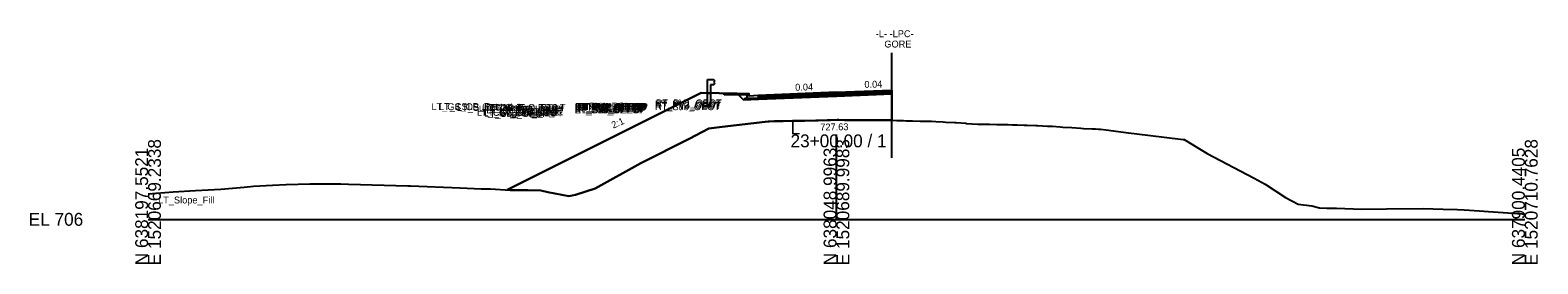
# Model space of a CAD drawing. Extents: x -26 to 3903, y -10 to 9531.
# Drawn here: x 974.3 to 1302.8, y 2990.3 to 3041.2 of the extents above; entities that cross this region are included whole.
import ezdxf

# ---------------------------------------------------------------- set-up
doc = ezdxf.new("R2010")
doc.units = 0
for name, color, linetype in [('Default', 7, 'Continuous'), ('Exist Cross Section Cell', 7, 'Continuous'), ('Exist XS Center Line Elevation Label', 7, 'Continuous'), ('Exist XS Ground Line', 7, 'Continuous'), ('Old_Level_63', 7, 'Continuous'), ('Prop CMT Conc Surface', 7, 'Continuous'), ('Prop CMT Guardrail Graphics', 7, 'Continuous'), ('Prop CMT Pvmt Course 1', 7, 'Continuous'), ('Prop CMT Pvmt Course 1 CG', 7, 'Continuous'), ('Prop CMT Pvmt Course 2', 7, 'Continuous'), ('Prop CMT Pvmt Course 3', 7, 'Continuous'), ('Prop CMT Pvmt Surface', 7, 'Continuous'), ('Prop CMT Shld Paved Course 1', 7, 'Continuous'), ('Prop CMT Shld Paved Course 2', 7, 'Continuous'), ('Prop CMT Shld Paved Course 3', 7, 'Continuous'), ('Prop CMT Slope Grass', 7, 'Continuous'), ('Prop CMT Subgrade Earthwork', 7, 'Continuous'), ('Prop XS Earthwork Shape', 7, 'Continuous'), ('Prop XS Finish Grade Concrete', 7, 'Continuous'), ('Prop XS SE Text', 7, 'Continuous'), ('Prop XS Shear Point Element', 7, 'Continuous'), ('Prop XS Side Slope Text', 7, 'Continuous')]:
    doc.layers.add(name, color=color, linetype=linetype)

msp = doc.modelspace()

# ---------------------------------------------------------------- linework, layer by layer
at = {"layer": 'Exist Cross Section Cell'}
for p, q in [((1150, 3000), (1150, 3018.49)), ((1000, 3000), (1150, 3000)), ((1150, 3000), (1300, 3000))]:
    msp.add_line(p, q, dxfattribs=at)
at = {"layer": 'Exist XS Ground Line'}
msp.add_lwpolyline([(1000, 3005.56), (1005.44, 3005.96), (1010.37, 3006.29), (1015.83, 3006.6), (1020.96, 3007.01), (1022.98, 3007.19), (1027.15, 3007.41), (1030.11, 3007.62), (1035.24, 3007.72), (1040, 3007.74), (1041.97, 3007.72), (1043.66, 3007.65), (1056.64, 3007.29), (1056.97, 3007.27), (1057.06, 3007.27), (1057.21, 3007.27), (1068.02, 3006.84), (1072.55, 3006.65), (1074.61, 3006.62), (1078.92, 3006.37), (1082.73, 3006.36), (1085.57, 3006.29), (1087.12, 3005.94), (1091.72, 3005.02), (1093.13, 3005.35), (1097.46, 3006.75), (1107.37, 3012.26), (1117.93, 3017.54), (1122.17, 3019.77), (1125.12, 3020.12), (1134.46, 3021.25), (1135.13, 3021.33), (1135.21, 3021.33), (1135.33, 3021.34), (1136.44, 3021.39), (1136.48, 3021.39), (1136.64, 3021.39), (1137.91, 3021.4), (1138.41, 3021.41), (1140.45, 3021.44), (1142.18, 3021.46), (1142.85, 3021.47), (1142.95, 3021.47), (1143.07, 3021.47), (1145.48, 3021.51), (1146.04, 3021.53), (1148, 3021.58), (1148.74, 3021.6), (1150.18, 3021.64), (1150.44, 3021.64), (1150.55, 3021.64), (1151.73, 3021.63), (1153.07, 3021.63), (1153.95, 3021.62), (1155.6, 3021.61), (1157.78, 3021.6), (1158.11, 3021.6), (1160.17, 3021.59), (1160.58, 3021.59), (1160.64, 3021.59), (1160.71, 3021.59), (1163.16, 3021.54), (1163.53, 3021.54), (1164.62, 3021.52), (1165.16, 3021.49), (1165.7, 3021.47), (1166.61, 3021.44), (1168.22, 3021.4), (1169.53, 3021.38), (1170.75, 3021.35), (1171.66, 3021.31), (1173.27, 3021.21), (1173.85, 3021.18), (1175.77, 3021.08), (1176.09, 3021.07), (1178.2, 3020.92), (1178.32, 3020.91), (1178.34, 3020.91), (1180.84, 3020.76), (1181.27, 3020.75), (1183.36, 3020.71), (1184.94, 3020.68), (1185.88, 3020.67), (1186.77, 3020.66), (1187.28, 3020.65), (1187.4, 3020.64), (1188.4, 3020.61), (1189.37, 3020.58), (1190.91, 3020.54), (1191.58, 3020.52), (1193.43, 3020.46), (1193.79, 3020.44), (1195.96, 3020.33), (1195.98, 3020.33), (1196.86, 3020.29), (1197.1, 3020.27), (1198.77, 3020.14), (1199.35, 3020.1), (1201.29, 3019.97), (1203.27, 3019.86), (1203.83, 3019.82), (1205.72, 3019.73), (1206.21, 3019.7), (1206.42, 3019.69), (1207.07, 3019.65), (1207.57, 3019.61), (1208.75, 3019.48), (1209.82, 3019.32), (1213.67, 3018.85), (1217.87, 3018.33), (1225.56, 3017.42), (1225.71, 3017.41), (1225.79, 3017.39), (1230.79, 3014.31), (1239.49, 3009.79), (1241.01, 3008.97), (1242.59, 3008.11), (1243.4, 3007.65), (1247.87, 3004.75), (1250.64, 3003.29), (1253.6, 3002.93), (1255.26, 3002.52), (1256.86, 3002.44), (1259, 3002.46), (1264.47, 3002.25), (1269.85, 3002.29), (1277.84, 3002.37), (1282.18, 3002.24), (1285.31, 3002.14), (1286.82, 3002.06), (1287.92, 3001.97), (1299.42, 3001.2), (1300, 3001.16)], dxfattribs=at)
at = {"layer": 'Old_Level_63'}
for p, q in [((1131.01, 3026.85), (1131.01, 3027.35)), ((1133.01, 3027.01), (1131.01, 3026.85)), ((1162.07, 3028.17), (1162.07, 3021.57))]:
    msp.add_line(p, q, dxfattribs=at)
for points in [[(1125.51, 3027.12), (1125.51, 3027.46)], [(1130.51, 3027.02), (1125.51, 3027.12)], [(1130.51, 3027.02), (1125.51, 3027.12)], [(1130.51, 3027.35), (1130.51, 3026.32), (1133.01, 3026.42)], [(1133.01, 3026.42), (1133.01, 3027.01)]]:
    msp.add_lwpolyline(points, dxfattribs=at)
at = {"layer": 'Prop CMT Conc Surface'}
for points in [[(1130.93, 3026.84), (1130.93, 3027.34), (1130.43, 3027.34)], [(1132.93, 3027), (1130.93, 3026.84)], [(1080.93, 3023.84), (1080.93, 3024.34), (1080.43, 3024.34)], [(1082.93, 3024), (1080.93, 3023.84)]]:
    msp.add_lwpolyline(points, dxfattribs=at)
at = {"layer": 'Prop CMT Guardrail Graphics'}
for points in [[(1121.9, 3024.47), (1121.9, 3030.47)], [(1121.9, 3030.47), (1123.23, 3030.47), (1123.5, 3030.18)], [(1123.5, 3029.6), (1123.23, 3029.31), (1122.56, 3029.31)], [(1122.56, 3029.31), (1122.56, 3024.47)], [(1123.5, 3030.18), (1123.23, 3029.89)], [(1123.23, 3029.89), (1123.5, 3029.6)], [(1122.54, 3027.39), (1121.87, 3027.39)], [(1122.56, 3024.47), (1121.9, 3024.47)]]:
    msp.add_lwpolyline(points, dxfattribs=at)
at = {"layer": 'Prop CMT Pvmt Course 1'}
for q in [(1133.01, 3027.01), (1162.07, 3028.17)]:
    msp.add_line((1150, 3027.69), q, dxfattribs=at)
for points in [[(1133.01, 3026.76), (1150, 3027.44)], [(1133.01, 3027.01), (1133.01, 3026.76)], [(1133.01, 3027.01), (1133.01, 3026.76)], [(1133.01, 3027.01), (1133.01, 3026.76)], [(1162.07, 3027.92), (1150, 3027.44)], [(1150, 3027.44), (1150, 3027.69)], [(1150, 3027.44), (1150, 3027.69)], [(1162.07, 3028.17), (1162.07, 3027.92)]]:
    msp.add_lwpolyline(points, dxfattribs=at)
msp.add_lwpolyline([(1150, 3027.44), (1150, 3027.56), (1150, 3027.56), (1150, 3027.44)], close=True, dxfattribs=at)
msp.add_lwpolyline([(1150, 3027.44), (1150, 3027.56), (1150, 3027.56), (1150, 3027.44)], close=True, dxfattribs=at)
at = {"layer": 'Prop CMT Pvmt Course 1 CG'}
for points in [[(1133.01, 3026.42), (1130.01, 3026.3), (1129.75, 3026.04)], [(1133.01, 3026.17), (1133.01, 3026.42)], [(1133.01, 3026.17), (1133.01, 3026.42)]]:
    msp.add_lwpolyline(points, dxfattribs=at)
at = {"layer": 'Prop CMT Pvmt Course 2'}
for points in [[(1150, 3027.44), (1133.01, 3026.76)], [(1133.01, 3026.42), (1150, 3027.1)], [(1133.01, 3026.76), (1133.01, 3026.42)], [(1133.01, 3026.76), (1133.01, 3026.42)], [(1133.01, 3026.76), (1133.01, 3026.42)], [(1150, 3027.44), (1162.07, 3027.92)], [(1162.07, 3027.59), (1150, 3027.1)], [(1150, 3027.1), (1150, 3027.44)], [(1150, 3027.1), (1150, 3027.44)], [(1162.07, 3027.92), (1162.07, 3027.59)]]:
    msp.add_lwpolyline(points, dxfattribs=at)
at = {"layer": 'Prop CMT Pvmt Course 3'}
for points in [[(1150, 3027.1), (1133.01, 3026.42)], [(1133.01, 3026.17), (1150, 3026.85)], [(1133.01, 3026.42), (1133.01, 3026.17)], [(1133.01, 3026.42), (1133.01, 3026.17)], [(1133.01, 3026.42), (1133.01, 3026.17)], [(1150, 3027.1), (1162.07, 3027.59)], [(1162.07, 3027.34), (1150, 3026.85)], [(1150, 3026.85), (1150, 3027.1)], [(1150, 3026.85), (1150, 3027.1)], [(1162.07, 3027.59), (1162.07, 3027.34)]]:
    msp.add_lwpolyline(points, dxfattribs=at)
at = {"layer": 'Prop CMT Pvmt Surface'}
msp.add_line((1133.01, 3027.01), (1162.07, 3028.17), dxfattribs=at)
for points in [[(1150, 3027.69), (1133.01, 3027.01)], [(1150, 3027.69), (1162.07, 3028.17)]]:
    msp.add_lwpolyline(points, dxfattribs=at)
at = {"layer": 'Prop CMT Shld Paved Course 1'}
msp.add_lwpolyline([(1133.01, 3026.76), (1133.01, 3027.01)], dxfattribs=at)
at = {"layer": 'Prop CMT Shld Paved Course 2'}
msp.add_lwpolyline([(1133.01, 3026.42), (1133.01, 3026.76)], dxfattribs=at)
at = {"layer": 'Prop CMT Shld Paved Course 3'}
msp.add_lwpolyline([(1133.01, 3026.17), (1133.01, 3026.42)], dxfattribs=at)
at = {"layer": 'Prop CMT Slope Grass'}
for points in [[(1120.5, 3027.55), (1078.23, 3006.41)], [(1130.51, 3027.36), (1120.5, 3027.55)], [(1162.07, 3028.17), (1162.07, 3021.57)]]:
    msp.add_lwpolyline(points, dxfattribs=at)
at = {"layer": 'Prop CMT Subgrade Earthwork'}
for points in [[(1133.01, 3026.17), (1129.75, 3026.04), (1128.4, 3027.39)], [(1150, 3026.85), (1133.01, 3026.17)], [(1150, 3026.85), (1162.07, 3027.34)]]:
    msp.add_lwpolyline(points, dxfattribs=at)
at = {"layer": 'Prop XS Earthwork Shape'}
for points in [[(1120.5, 3027.55), (1078.23, 3006.41), (1078.92, 3006.37), (1082.73, 3006.36), (1085.57, 3006.29), (1087.12, 3005.94), (1091.72, 3005.02), (1093.13, 3005.35), (1097.46, 3006.75), (1107.37, 3012.26), (1117.93, 3017.54), (1122.17, 3019.77), (1125.12, 3020.12), (1134.46, 3021.25), (1135.13, 3021.33), (1135.33, 3021.34), (1136.44, 3021.39), (1136.64, 3021.39), (1137.91, 3021.4), (1138.41, 3021.41), (1140.45, 3021.44), (1142.18, 3021.46), (1142.85, 3021.47), (1143.07, 3021.47), (1145.48, 3021.51), (1146.04, 3021.53), (1148, 3021.58), (1148.74, 3021.6), (1150.18, 3021.64), (1150.44, 3021.64), (1150.55, 3021.64), (1151.73, 3021.63), (1153.07, 3021.63), (1153.95, 3021.62), (1155.6, 3021.61), (1157.78, 3021.6), (1158.11, 3021.6), (1160.17, 3021.59), (1160.58, 3021.59), (1160.71, 3021.59), (1162.07, 3021.57), (1162.07, 3027.34), (1150, 3026.85), (1133.01, 3026.17), (1129.75, 3026.04), (1128.4, 3027.39)], [(1150, 3026.85), (1162.07, 3027.34), (1162.07, 3021.57), (1160.71, 3021.59), (1160.58, 3021.59), (1160.17, 3021.59), (1158.11, 3021.6), (1157.78, 3021.6), (1155.6, 3021.61), (1153.95, 3021.62), (1153.07, 3021.63), (1151.73, 3021.63), (1150.55, 3021.64), (1150.44, 3021.64), (1150.18, 3021.64), (1148.74, 3021.6), (1148, 3021.58), (1146.04, 3021.53), (1145.48, 3021.51), (1143.07, 3021.47), (1142.85, 3021.47), (1142.18, 3021.46), (1140.45, 3021.44), (1138.41, 3021.41), (1137.91, 3021.4), (1136.64, 3021.39), (1136.44, 3021.39), (1135.33, 3021.34), (1135.13, 3021.33), (1134.46, 3021.25), (1125.12, 3020.12), (1122.17, 3019.77), (1117.93, 3017.54), (1107.37, 3012.26), (1097.46, 3006.75), (1093.13, 3005.35), (1091.72, 3005.02), (1087.12, 3005.94), (1085.57, 3006.29), (1082.73, 3006.36), (1078.92, 3006.37), (1078.23, 3006.41), (1120.5, 3027.55), (1128.4, 3027.39), (1129.75, 3026.04), (1133.01, 3026.17)]]:
    msp.add_lwpolyline(points, close=True, dxfattribs=at)
at = {"layer": 'Prop XS Finish Grade Concrete'}
msp.add_lwpolyline([(1133.01, 3027.01), (1131.01, 3026.85), (1131.01, 3027.35), (1130.51, 3027.35)], dxfattribs=at)
at = {"layer": 'Prop XS Shear Point Element'}
msp.add_line((1162.07, 3013.37), (1162.07, 3036.3), dxfattribs=at)

# ---------------------------------------------------------------- texts
at = {"layer": 'Default'}
msp.add_text('-', height=0.0001, dxfattribs=at).set_placement((1000, 3000))
at = {"layer": 'Exist Cross Section Cell'}
for s, p in [('L', (1140, 3018.49)), ('23+00.00 / 1', (1140, 3015.69)), ('EL 706', (974, 2998.6))]:
    msp.add_text(s, height=2.8, dxfattribs=at).set_placement(p)
for s, p in [('E 1520669.2338', (1002.8, 2990)), ('E 1520689.9983', (1152.8, 2990)), ('E 1520710.7628', (1302.8, 2990)), ('N 638197.5521', (1000, 2990)), ('N 638048.9963', (1150, 2990)), ('N 637900.4405', (1300, 2990))]:
    msp.add_text(s, height=2.8, rotation=90, dxfattribs=at).set_placement(p)
at = {"layer": 'Exist XS Center Line Elevation Label'}
msp.add_text('727.63', height=1.5, rotation=0.8401, dxfattribs=at).set_placement((1146.49, 3019.34))
at = {"layer": 'Prop CMT Conc Surface'}
for s, p in [('RT_PV2_OEOT', (1110.45, 3024.36)), ('RT_PV1_OEOT', (1110.63, 3024.61)), ('LT_GS_OS_Tentative', (1061.76, 3023.78)), ('LT_CSLP_Pnt', (1063.38, 3023.82)), ('LT_Sub_Trench_Out_DLT', (1067.3, 3023.63)), ('LT_CG1_Shelf_Out', (1071.67, 3022.55)), ('LT_CG_Top_BOC', (1072.79, 3023.59)), ('LT_CG_Bot_BOC', (1073, 3022.57)), ('LT_CG_Top_Face', (1073.31, 3023.59)), ('LT_Sub_OEOP', (1073.32, 3022.29)), ('LT_CG_Top_Gut', (1073.71, 3023.09)), ('LT_PV2_OEOT', (1076.55, 3023)), ('LT_PV3_OEOT', (1076.55, 3022.67)), ('LT_Sub_OEOT', (1076.59, 3022.42)), ('LT_PV1_OEOT', (1076.73, 3023.25)), ('LT_CG_Bot_IE', (1076.81, 3022.67)), ('RT_PV2_OEEOP', (1092.93, 3023.68)), ('RT_PV3_OEEOP', (1092.93, 3023.35)), ('RT_Sub_OEEOP', (1092.96, 3023.1)), ('LT_PV2_OEEOP', (1093.01, 3023.68)), ('LT_PV3_OEEOP', (1093.01, 3023.35)), ('LT_Sub_OEEOP', (1093.05, 3023.1)), ('RT_PV1_OEEOP', (1093.11, 3023.81)), ('LT_PV1_OEEOP', (1093.19, 3023.81)), ('RT_PV2_IEEOP', (1093.5, 3023.68)), ('LT_PV2_IEEOP', (1093.58, 3023.68)), ('RT_PV1_IEEOP', (1093.68, 3023.81)), ('LT_PV1_IEEOP', (1093.76, 3023.81)), ('PV2_PGL', (1095.95, 3023.68)), ('PV1_PGL', (1096.13, 3023.93)), ('RT_PV3_OEOT', (1110.45, 3024.03)), ('RT_Sub_OEOT', (1110.48, 3023.78)), ('LT_Slope_Fill', (1002.19, 3003.46))]:
    msp.add_text(s, height=1.5, dxfattribs=at).set_placement(p)
at = {"layer": 'Prop XS SE Text'}
for s, rotation, p in [('-L- -LPC-', 359.9946, (1158.58, 3039.68)), ('GORE', 359.9946, (1160.44, 3037.43)), ('0.04', 1.1458, (1141.02, 3028.02)), ('0.04', 1.1458, (1156.11, 3028.64))]:
    msp.add_text(s, height=1.5, rotation=rotation, dxfattribs=at).set_placement(p)
at = {"layer": 'Prop XS Side Slope Text'}
msp.add_text('2:1', height=1.5, rotation=23.9099, dxfattribs=at).set_placement((1101.37, 3019.74))

doc.saveas('drawing.dxf')
